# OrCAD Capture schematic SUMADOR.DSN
size A
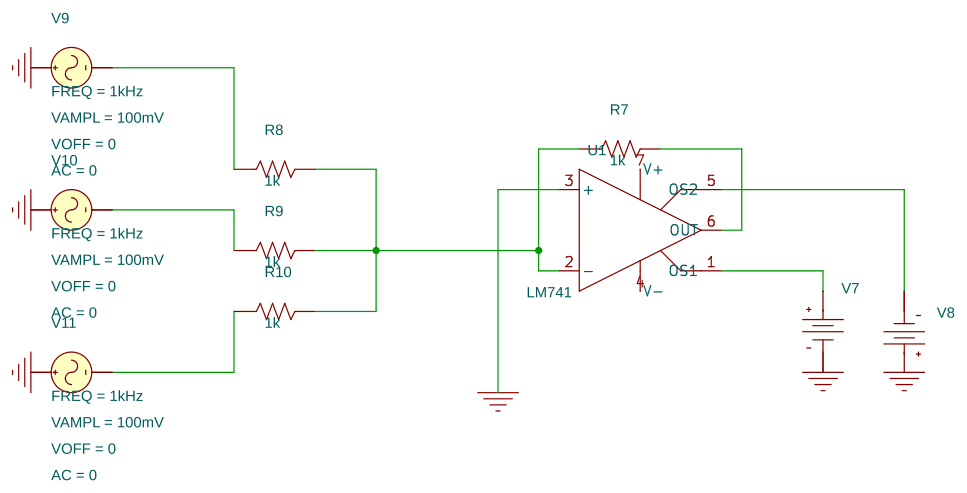
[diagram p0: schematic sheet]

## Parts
R7  1k  [AX/RC05]
R8  1k  [AX/RC05]
R9  1k  [AX/RC05]
R10  1k  [AX/RC05]
U1  LM741  [DIP.100/8/W.300/L.450]
V7  VDC
V8  VDC
V9  VSIN
V10  VSIN
V11  VSIN

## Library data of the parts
R7-R10 = r
U1 = LM741
V7 V8 = VDC
V9-V11 = VSIN: AC: 0; FREQ: 1kHz; VAMPL: 100mV; VOFF: 0

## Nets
0: U1.3(+) V7.1(-) V8.0(+) V9.1(+) V10.1(+) V11.1(+)
V+: U1.7(V+)
V-: U1.4(V-)
N00411: R7.1 R8.2 R9.2 R10.2 U1.2(-)
N00443: R7.2 U1.6(OUT)
N03075: U1.5(OS2) V8.1(-)
N03082: U1.1(OS1) V7.0(+)
N05446: R8.1 V9.2(-)
N05453: R9.1 V10.2(-)
N05460: R10.1 V11.2(-)
